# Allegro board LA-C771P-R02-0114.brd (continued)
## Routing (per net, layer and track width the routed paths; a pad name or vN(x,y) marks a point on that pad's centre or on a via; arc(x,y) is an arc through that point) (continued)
GNDA: length 136.1
  TOP w0.102: v3(31.78,19.95) 31.78,20.47 v2(31.88,20.56) ; v2(14.32,12.93) 13.96,13.29 RA24.2 ; v3(28.48,15.12) v2(28.48,14.45)
  TOP w0.203: UA1.25 22.57,21.1 22.48,21.01 22.23,21.01 v3(21.97,21.27)
  TOP w0.254: v3(17.91,17.63) 18.19,17.36 RA14.1 ; UA1.38 28.65,22.68 v3(28.73,22.59)
  TOP w0.381: 22.31,19.06 v3(22.31,18.98) ; 22.31,19.06 22.68,19.43 22.68,19.53 CA20.2 ; 22.31,19.06 22.26,19.01 21.65,19.01 CA16.1 ; RA22.1 v3(27.19,15.12) ; v3(31.4,20.96) 31.33,20.96 30.46,21.83 CA9.2 ; v3(28.48,15.12) RA23.1
  TOP w0.457: v3(15.42,25.03) 15.65,25.26 RA21.2
  TOP w0.508: RA28.2 31.96,19.77 v3(31.78,19.95) ; CA8.2 17.13,19.28 CA7.2 v3(17.1,20.02) ; v3(12.41,13.29) 12.41,13.29 RA24.2 ; RA26.2 v3(30.01,15.76) ; CA11.2 13.14,14.46 CA14.2 12.27,14.44 v3(12.27,14.44)
  IN1 w1.016: 17.48,26.86 18.27,27.64 18.27,32.5 22.41,36.64 22.41,50.28 27.26,55.13 27.26,73.67 26.14,74.79 ; 26.5,78.39 27.41,78.39 29.55,76.26 29.55,54.18 24.7,49.33 24.7,35.7 20.56,31.56 20.56,26.17 v3(20.43,26.04) 19.82,25.43 19.82,23.68 19.64,23.51 19.64,21.93 20.3,21.27 v3(21.97,21.27)
  BOTTOM w0.381: v3(15.27,19.57) 15.53,19.82 CA17.2 15.53,20.18 14.64,20.18 CA19.2
  vias: v3(0.52,21.83) v3(0.49,13.95) v3(1.73,19.39) v3(1.73,16.32) v3(4.05,19.14) v3(4.61,22.39) v3(5.67,20.51) v3(6.79,22.31) v3(7.4,19.24) v3(9.53,16.16) v3(17.1,20.84) v3(25.23,75.14) v3(25.26,74.46) v3(25.38,78.83) v3(25.36,78.16)
VCC_3.3V: length 2.9
  BOTTOM w0.102: v2(50.45,47.84) 50.31,47.98 48.57,47.98 PC320.1
VDD_DDR: length 1.5
  BOTTOM w0.102: 155.58,27.82 156.04,27.36 v2(156.88,27.36)
VIN: length 334.3
  TOP w0.102: v2(44.29,58.18) 44.29,58.17 43.72,58.75 v3(43.72,59.37) v2(43.72,60.14) ; v3(202.92,76.53) 202.33,76.53 201.95,76.15 v2(201.95,76.15)
  IN1 w0.508: v3(43.72,59.37) 43.07,60.02 43.07,66.27 44.7,67.9 44.7,74.27 36.69,82.28 36.69,85.15 43.21,91.68 v3(43.21,94.48)
  IN2 w0.508: v3(43.72,59.37) 43.47,59.12 43.47,55.9 35.33,47.76 34.83,47.26 34.83,35.29 42.58,27.54 43.82,27.54 57.6,13.76 61.08,13.76 63.08,11.76 69.98,11.76 70.38,12.15 77.54,12.15 79.42,14.03 86.03,14.03 86.52,13.53 90.15,13.53 91.3,12.38 103.65,12.38 105.36,14.09 125.31,14.09 129.69,9.71 164.47,9.71 179.5,24.74 179.5,28.76 183.11,32.38 183.11,42.02 185.25,44.15 185.25,57.63 178.23,64.66 178.23,64.69 178.06,64.86 178.06,81.61 180.91,84.46 199.63,84.46 202.52,81.57 202.52,76.92 v3(202.92,76.53)
  BOTTOM w0.508: v3(202.92,76.53) PR215.1 202.23,77.62 PD1.3
+CARD_3V3: length 3.6
  TOP w0.102: v2(47.7,20.71) 47.7,20.71 v3(46.21,20.71) ; v2(45.55,20.04) 45.55,20.05 v3(46.21,20.71) ; v3(46.21,20.71) 46.21,21.86 v2(46.2,21.87)
+CARD_3V3_R: length 0.8
  TOP w0.254: UR1.10 v3(44.53,13.23)
  vias: v2(51.19,21.5)
+CHGRTC: length 4.6
  TOP w0.102: v3(145.33,18.2) v2(145.33,18.79)
  BOTTOM w0.508: v3(145.33,18.2) 145.95,18.2 146.6,17.55 PD100.2 147.88,17.92 PR115.1
+CHGRTC_R: length 11
  TOP w0.102: v3(151.68,16.52) 151.68,17.12 v2(151.68,17.12)
  BOTTOM w0.508: JRTC1.1 158.82,16.52 v3(151.68,16.52) PR116.2
+DDR_A_VREF_CA: length 4.8
  TOP w0.254: v3(107.13,40.13) 107.13,39.68 106.84,39.39 CD3.1 106.84,38.13 RD3.2 RD4.2
  BOTTOM w0.356: JDIMM1.126 107.03,40.05 107.12,40.14 107.12,40.13 v3(107.13,40.13)
+DDR_A_VREF_DQ: length 9
  TOP w0.508: v3(67.47,43.82) 68.11,43.82 68.5,44.22 68.5,45.73 68.22,46.01 RD2.2 68.22,46.33 CD1.1 68.24,47.23 RD1.2
  BOTTOM w0.356: v3(67.47,43.82) 67.16,43.82 66.58,44.4 66.58,45.25 67.13,45.8 JDIMM1.1
+DDR_SOC_VREF: length 14.2
  IN1 w0.254: v3(110.6,68.76) 110.64,68.76 114.55,64.86 117.08,64.86 117.71,64.22 v3(117.71,63.89)
  BOTTOM w0.254: UC4.AF44 110.25,69.12 v3(110.6,68.76)
  BOTTOM w0.508: v3(117.71,63.89) 117.33,63.51 116.75,63.51 116.11,62.87 CC1.1 116.12,62.39 RC7.2 RC6.2
+EC_VCCA: length 40.7
  TOP w0.203: 66.33,10.29 66.53,10.49 UB1.67
  TOP w0.508: v3(67.77,15.88) 67.77,15.5 66.78,14.51 66.3,14.51 64.62,12.83 64.62,12.27 63.53,11.18 62.31,11.18 v2(60.49,9.36) 60.08,8.95 v3(60.08,8.46) ; v3(81.67,18.6) 82.02,18.95 PR110.1 ; v3(65.23,7.93) 65.23,7.52 L3.2 66.26,7.63 CB1.1 66.25,8.27 CB2.1 65.95,9.45 65.95,9.91 66.33,10.29
  IN1 w0.508: v3(60.08,8.46) 60.61,7.93 v3(65.23,7.93)
  BOTTOM w0.508: v3(67.77,15.88) 69.76,17.87 71.58,17.87 72.88,16.57 79.64,16.57 v3(81.67,18.6)
+HDMI_5V_OUT: length 6
  BOTTOM w0.102: v2(14.39,96.25) 14.38,96.25 14.38,95.41 ; v2(16.15,96.16) 15.12,96.16 14.73,95.77 14.73,95.5 ; v2(16.81,94.46) 15.3,94.46
  BOTTOM w0.254: RPY1.2 17.55,90.19 v3(17.33,90.41) 17.05,90.13 RPY1.1
  vias: v3(12.86,94.5) v3(13.16,95.03) v3(13.37,94.12) v3(13.55,90.64) v3(13.6,90.03)
+INVPWR_B+:
  vias: v2(75.05,98.21) v3(66.81,98.76) v3(67.4,98.76) v3(72.25,100.75) v3(73.85,100.82) v3(73.82,100.19)
+IOVDD_CODEC: length 1
  TOP w0.254: UA1.9 23.77,28.53 v3(23.81,28.56)
+LAN_VDD: length 5.5
  TOP w0.508: CL5.1 35.57,66.24 v3(35.07,65.74)
  BOTTOM w0.203: v3(35.07,65.74) 35.07,66.71 UL1.30 ; CL6.1 39.82,67.67 39.73,67.67 39.17,68.23 38.54,68.23 38.46,68.15 UL1.22 ; UL1.3 32.77,68.15 v3(32.7,68.08)
  vias: v2(33.41,66.58) v3(32.75,69.63) v3(32.8,70.21) v3(38.36,66.4) v3(38.7,65.92) v3(38.95,66.46)
+LCDVDD: length 9.8
  TOP w0.127: v2(68.96,85.01) 69.87,85.01 71.46,86.6 ; v2(67.13,85.19) 67.36,85.42 69.73,85.42 71.18,86.86 71.31,86.86 ; v2(70.77,85.21) 71.97,86.41 UX1.1
  vias: v3(63.07,98.76) v3(63.65,98.76) v3(64.24,98.76) v3(64.83,98.78) v3(68.38,91.27) v3(68.41,90.69) v3(69.02,91.27) v3(69.02,90.69) v3(69.63,90.66)
+LINE1-VREFO-L: length 6.9
  TOP w0.203: UA1.31 24.97,20.38 25.48,19.87 v2(25.48,19.59) 25.48,19.37 26.07,18.79 RA25.1 25.56,18.17 25.56,17.38 26.51,16.43 v3(26.55,16.43)
  BOTTOM w0.203: v3(26.55,16.43) 26.25,16.73 RA29.1
+LINE1-VREFO-R: length 1.6
  TOP w0.203: UA1.30 24.57,19.97 RA27.2
+MIC2-VREFO: length 12.4
  TOP w0.203: v3(24.11,20.63) 24.11,20.64 24.16,20.64 24.16,20.69 24.17,20.7 UA1.29
  TOP w0.508: v3(17.81,24.77) RA7.1 RA6.1
  IN2 w0.508: v3(24.11,20.63) 24.11,21.14 23.86,21.4 22.82,21.4 21.6,22.61 21.6,24.7 20.96,25.33 18.37,25.33 v3(17.81,24.77)
+RTCVCC: length 262.4
  TOP w0.508: CC23.1 93.88,92.84 v3(94.01,92.72) 94.01,90.29 93.07,89.34 93.07,88.37 v3(92.98,88.28) 89.87,88.28 89.16,88.99 v3(89.16,89.72) ; v3(118.22,17.99) 118.22,7.63 v2(116.31,5.72) 115.27,4.68 102.52,4.68 101.4,3.56 97.84,3.56 95.42,5.98 v3(93.84,5.98)
  IN1 w0.508: v3(89.16,89.72) 89.16,88.34 88.5,87.68 87.05,87.68 83.6,84.23 81.47,84.23 80.86,83.62 74.42,83.62 73.43,82.62 70.87,82.62 68.23,79.98 67.2,79.98 62.27,75.05 61.43,75.05 61.42,75.04 61.33,75.04 58.37,72.07 56.34,72.07 55.62,72.8 v3(55.62,73.44) ; v3(43.8,73.08) 43.8,68.13 42.22,66.56 42.22,53.02 35.14,45.93 35.14,33.22 37.19,31.17 37.19,27.85 39.94,25.1 39.94,13.07 41.89,11.12 43.03,11.12 44.61,9.53 53.02,9.53 55.46,7.1 65.51,7.1 66.04,7.63 72.53,7.63 73.24,8.34 81.16,8.34 82.23,9.41 82.23,10.24 82.58,10.6 83.09,10.6 83.89,9.8 88.59,9.8 92.41,5.98 v3(93.84,5.98)
  IN2 w0.508: v3(118.22,17.99) 127.64,17.99 v3(129.88,15.76)
  BOTTOM w0.254: UC4.P22 104.7,80.13 v3(104.7,80.37)
  BOTTOM w0.508: RC47.1 92.88,87.65 RC49.1 92.88,88.18 v3(92.98,88.28) ; v3(129.88,15.76) 130.47,15.17 144.19,15.17 PD100.1 ; v3(55.62,73.44) 55.62,73.44 53.75,73.44 52.71,72.4 44.48,72.4 v3(43.8,73.08)
+SOC_VCC: length 1
  BOTTOM w0.508: PC768.2 127.57,69.76 v3(127.06,69.25)
  vias: v2(141.08,73.72) v3(104.8,77.5) v3(105.72,76.31) v3(105.77,77.07) v3(106.49,77.06) v3(106.5,76.29) v3(107.32,76.31) v3(108.09,77.84) v3(108.06,77.1) v3(108.08,76.31) v3(108.85,77.83) v3(108.88,76.31) v3(109.66,77.78) v3(109.66,77.07) v3(110.42,77.78) v3(110.44,77.07) v3(110.44,76.31) v3(118.74,76.42) v3(119.44,76.43) v3(120.19,72.59) v3(122.1,71.71) v3(123.78,68.67) v3(123.76,67.75) v3(135.03,72.72) v3(135.67,72.72) v3(136.56,72.72) v3(137.52,72.66) v3(138.18,72.66) v3(139.1,72.65) v3(139.81,72.64) v3(142.8,73.97) v3(142.83,73.28) v3(143.06,71.28) v3(143.06,70.62) v3(143.08,69.65) v3(143.08,68.99) v3(143.49,73.33) v3(143.59,73.97) v3(144.15,73.33) v3(144.23,68.43) v3(144.25,73.97) v3(144.25,69.17) v3(144.81,73.33) v3(144.94,74) v3(144.94,68.43) v3(144.96,69.17) v3(145.5,73.31) v3(145.6,74) v3(145.65,69.17) v3(145.62,68.43) v3(146.34,69.14) v3(146.31,68.41)
+SOC_VNN: length 2.4
  TOP w0.508: v3(122.92,81.08) 122.92,81.46 122.61,81.77 121.16,81.77 RC71.1
  vias: v2(140.98,77.91) v3(108.85,80.1) v3(108.88,79.34) v3(109.66,79.37) v3(110.45,79.35) v3(110.45,78.59) v3(111.22,79.35) v3(111.97,80.1) v3(112.01,79.35) v3(112.78,80.12) v3(112.77,79.35) v3(112.77,77.82) v3(112.79,77) v3(112.79,76.26) v3(112.78,75.56) v3(129.98,81.82) v3(129.98,81.03) v3(129.98,80.1) v3(129.95,79.33) v3(134.93,79.13) v3(134.97,77.67) v3(135.62,79.1) v3(135.61,77.67) v3(136.74,79.13) v3(136.69,77.73) v3(137.35,77.76) v3(137.4,79.13) v3(138.08,79.14) v3(138.07,77.76) v3(138.74,79.14) v3(138.73,77.78) v3(140.11,80.78) v3(140.3,80.07) v3(140.84,80.81) v3(140.96,80.07) v3(141.6,80.78) v3(141.62,80.07) v3(142,79.34) v3(142.31,80.04) v3(142.43,80.77) v3(142.65,79.32) v3(142.97,80.04) v3(143.12,80.77) v3(143.49,79.39) v3(143.63,80.04) v3(143.8,80.78) v3(144.15,79.37) v3(144.29,80.1)
+USB3_VCCA: length 3.8
  TOP w0.102: v2(22.68,33.63) 22.68,35.38 22.78,35.48
  BOTTOM w0.381: DS2.5 v3(20.42,44.7)
  BOTTOM w0.508: DS3.5 v3(17.46,35.37)
  vias: v2(22.12,35.26) v2(23.71,36) v3(19.34,39.2) v3(19.34,38.44) v3(20.05,39.18) v3(19.97,38.49) v3(20.68,39.2) v3(20.68,38.52)
+USB_SB:
  vias: v2(184.67,51.57) v3(186.24,53.86) v3(186.24,53.09) v3(186.24,52.33) v3(186.24,51.57) v3(186.24,50.68) v3(197.14,54.82) v3(198.03,54.82) v3(199.04,54.85) v3(200.13,54.82) v3(201.1,54.8)
ACDRV: length 322.4
  IN1 w0.508: v3(38.62,82.23) 38.62,81.25 45.33,74.53 45.33,67.63 43.88,66.18 43.88,60.22 44.38,59.72 44.38,59.04 v3(44.28,58.94)
  IN2 w0.508: v3(200.24,74.58) 200.49,74.58 201.13,75.22 203.36,75.22 203.92,75.78 203.92,77.66 203.51,78.06 203.51,81.8 199.91,85.4 180.95,85.4 177.43,81.87 177.43,64.59 177.59,64.43 177.59,64.39 184.61,57.37 184.61,44.42 182.48,42.28 182.48,32.66 178.86,29.05 178.86,25 164.21,10.35 129.95,10.35 125.57,14.73 105.1,14.73 103.38,13.01 91.57,13.01 90.41,14.17 86.78,14.17 86.29,14.66 79.15,14.66 77.27,12.79 70.11,12.79 69.72,12.39 63.35,12.39 61.34,14.39 57.86,14.39 44.06,28.2 42.82,28.2 35.59,35.43 35.59,47.13 44.28,55.82 v3(44.28,58.94)
  BOTTOM w0.203: PU1.4 200.38,74.23 200.24,74.37 v3(200.24,74.58)
  BOTTOM w0.508: v3(38.62,82.23) 38.92,82.23 39.53,82.84 PR209.2
ACN: length 359.9
  IN2 w0.254: v3(198.28,77.16) 198.28,77.46 199.42,78.6 200.11,78.6 200.57,79.05 200.57,80.17 198.61,82.13 188.91,82.13 186.67,79.89 183.95,79.89 181.39,77.33 181.39,67.09 184.61,63.86 197.9,63.86 198.48,63.29 202.46,63.29 204.83,60.92 204.83,31.03 179.94,6.13 128,6.13 123.85,10.28 108.96,10.28 108.46,10.78 91.59,10.78 89.73,12.65 86.15,12.65 85.66,13.14 79.82,13.14 77.94,11.26 70.75,11.26 70.35,10.87 62.42,10.87 60.56,12.73 57.1,12.73 43.66,26.17 42.52,26.17 33.81,34.88 33.81,50.41 37.3,53.89 38.78,53.89 41.66,56.78 41.66,59.98 46.66,64.98 48.34,64.98 48.75,65.39 48.75,68.31 49,68.56 49,74.58 v3(49.36,74.94)
  BOTTOM w0.203: PC210.1 198.8,73.78 199.18,73.41 PU1.1
  BOTTOM w0.254: v3(49.36,74.94) 49.18,74.76 45.58,74.76 44.87,75.46 40.78,75.46 39.2,77.05 v2(39.2,77.58) 39.2,79.1 39.28,79.18 39.28,81.01 39.71,81.44 41.87,81.44 42.07,81.24 PR202.3 ; PC210.1 198.84,74.41 PC208.2 198.45,75.64 198.45,75.67 PC209.1 198.28,76.48 v3(198.28,77.16)
ACP: length 360.9
  IN2 w0.254: v3(198.98,77.17) 198.98,77.62 199.58,78.22 200.27,78.22 200.95,78.9 200.95,80.33 198.77,82.51 188.75,82.51 186.51,80.27 183.8,80.27 181.01,77.48 181.01,66.93 184.46,63.48 197.75,63.48 198.32,62.91 202.3,62.91 204.45,60.76 204.45,31.18 179.78,6.51 128.16,6.51 124,10.66 109.11,10.66 108.62,11.16 91.75,11.16 89.89,13.03 86.31,13.03 85.81,13.52 79.66,13.52 77.78,11.64 70.59,11.64 70.19,11.25 62.58,11.25 60.71,13.12 57.26,13.12 43.82,26.55 42.68,26.55 34.19,35.04 34.19,50.25 37.46,53.51 38.94,53.51 42.04,56.62 42.04,59.83 46.82,64.6 48.5,64.6 49.13,65.23 49.13,68.15 49.39,68.41 49.39,74.08 v3(49.79,74.48)
  BOTTOM w0.203: PC208.1 199.36,74.86 199.36,73.73 199.58,73.52 PU1.2
  BOTTOM w0.254: PR202.2 42.07,82.03 41.87,81.82 39.55,81.82 38.82,81.09 v2(38.82,79.46) 38.82,77.85 38.74,77.77 38.74,77.39 38.82,77.31 38.82,76.89 40.62,75.08 44.71,75.08 45.42,74.38 49.69,74.38 v3(49.79,74.48) ; v3(198.98,77.17) PC207.2 199.38,75.94 199.38,75.63 PC208.1
ADP_I: length 222.9
  TOP w0.203: v3(63.33,9.56) 63.89,10.12 64.87,10.12 65.73,10.98 UB1.65
  TOP w0.254: PR112.2 88.73,14 92.74,9.99 93.99,9.99 v3(94.65,9.33) ; v3(201.9,73.86) 201.9,73.48 201.58,73.16
  IN2 w0.254: v3(63.33,9.56) 64.22,10.45 70.62,10.45 71.05,10.88 78.1,10.88 79.98,12.76 85.5,12.76 85.99,12.26 89.57,12.26 91.49,10.35 93.63,10.35 v3(94.65,9.33) 95.71,10.4 108.3,10.4 108.8,9.9 123.69,9.9 127.95,5.63 179.98,5.63 207.2,32.85 207.2,40.56 205.85,41.91 205.85,64.12 204.25,65.72 204.25,72.98 203.28,73.95 201.99,73.95 v3(201.9,73.86)
  BOTTOM w0.203: PU1.7 201.58,73.41 201.9,73.73 v3(201.9,73.86)
APDIN: length 4.6
  TOP w0.102: v3(39.3,100.94) 39.28,100.94 38.96,101.25 37.09,101.25 v2(37.03,101.19) ; v3(39.3,100.94) 40.08,100.94 v2(40.18,101.04) ; v3(39.3,100.94) 38.49,100.12 v2(38.43,100.12)
APDIN1:
  vias: v2(49.08,97.95)
B+:
  vias: v2(176.68,75.47) v2(181.25,78.24) v2(181.73,73.39) v3(46.12,52.94) v3(46.76,52.94) v3(47.39,52.94) v3(48.03,52.91) v3(49.31,75.8) v3(49.82,76.21) v3(50.25,76.69) v3(50.4,75.88) v3(50.71,77.17) v3(50.83,76.36) v3(56.42,53.17) v3(56.93,50.86) v3(57.09,48.14) v3(57.18,53.15) v3(57.18,52.46) v3(57.31,48.78) v3(57.56,50.43) v3(57.75,52.74) v3(57.82,49.79) v3(57.76,48.33) v3(58.2,52.21) v3(137.45,28.41) v3(137.37,27.69) v3(137.4,27.06) v3(138.13,28.41) v3(138.16,29.12) v3(138.16,27.75) v3(138.21,27.01) v3(138.8,28.46) v3(138.8,27.78) v3(138.87,29.8) v3(138.89,29.09) v3(175.93,47.9) v3(175.93,43.43) v3(175.95,47.14) v3(175.95,46.38) v3(175.95,45.41) v3(175.95,44.34) v3(175.95,42.46) v3(176.69,47.97) v3(176.72,46.48) v3(176.69,45.43) v3(176.72,44.39) v3(176.67,43.45) v3(176.72,42.52) v3(176.77,47.16)
BA+: length 19.1
  TOP w0.102: v2(194.45,76.27) 194.39,76.34 v3(192.63,76.34)
  IN2 w0.508: v3(187.49,77.42) 190.53,80.46 198.8,80.46 v3(199.73,79.54)
  BOTTOM w0.508: PC201.2 v3(187.49,77.42) ; PD1.2 201.61,79.54 v3(199.73,79.54)
  vias: v3(191.93,76.34) v3(191.93,75.64) v3(191.93,74.94) v3(191.93,74.24) v3(192.63,75.64) v3(192.63,74.94) v3(192.63,74.24)
BATDRV: length 30.7
  TOP w0.254: v3(201.77,67.45) 203.06,67.45 204.81,69.19 204.81,72.43 204.26,72.98 v2(204.26,76.82) 204.26,79.44 203.04,80.65 192.07,80.65 PR212.2
  BOTTOM w0.203: PU1.18 200.38,68.33 201.26,67.45 v3(201.77,67.45)
BATSRC: length 28.4
  TOP w0.254: v3(202.22,67.95) 203.03,67.95 204.38,69.3 204.38,72.32 203.78,72.92 v2(203.78,78.57) 203.78,79.22 202.73,80.27 192.68,80.27 v3(192.04,79.64)
  BOTTOM w0.203: v3(202.22,67.95) 201.26,67.95 200.78,68.44 PU1.17
  BOTTOM w0.254: v3(192.04,79.64) PR213.2
BATT+:
  vias: v2(200.21,83.98) v3(195.3,79.4) v3(195.27,78.74) v3(195.27,78.08) v3(195.27,77.42) v3(196.02,79.4) v3(195.99,78.74) v3(195.99,78.08) v3(195.99,77.42)
BATT_CHG_LED#: length 63.2
  TOP w0.102: UB1.90 75.73,10.69 76.59,9.83 76.59,7.37 76.37,7.15 76.37,5.38 75.01,4.02 v3(75.01,3.89) ; R15.1 25.08,6.89 v3(25.69,6.89)
  IN2 w0.127: v3(25.69,6.89) 28.48,6.89 29.27,6.1 31.77,6.1 35.78,2.1 74.09,2.1 75.01,3.02 v3(75.01,3.89)
BATT_LOW_LED#: length 71.3
  TOP w0.102: 77.28,10.52 76.93,10.87 UB1.93 ; 77.28,10.52 77.28,10.52 77.27,10.52 77.27,7.09 77.05,6.87 77.05,4.21 v3(76.82,3.97) ; 77.28,10.52 v2(77.28,10.33) ; LED2.1 v3(20.75,1.6)
  IN2 w0.127: v3(76.82,3.97) 76.82,3.75 74.4,1.33 31.8,1.33 29.09,4.05 29.09,5.11 28.17,6.03 25.38,6.03 20.95,1.6 v3(20.75,1.6)
BEEP#: length 55.7
  TOP w0.102: UB1.23 69.33,26.34 69.68,25.99 v3(69.68,21.42)
  BOTTOM w0.102: CA30.1 25.31,29.5 25.92,30.11 29.32,30.11 v2(29.47,30.26) 34.27,30.26 37.05,27.49 55.84,27.49 57.3,26.03 61.02,26.03 61.41,25.64 61.41,25.26 62.4,24.26 65.31,24.26 68.16,21.42 v3(69.68,21.42)
BKOFF#: length 56.8
  TOP w0.102: RPC1.5 79.56,75.09 79.43,74.96 79.43,74.58 78.53,73.67 78.53,73.26 73.84,68.57 67.79,68.57 67.65,68.72 65.61,68.72 64.89,69.44 63.64,69.44 61.87,71.21 61.87,76.64 59.66,78.85 57.16,78.85 55.91,77.61 54.13,77.61 v3(53.86,77.88)
  IN1 w0.127: v3(53.86,77.88) 53.5,78.24 53.5,85.05 50.33,88.22 50.33,91.14 v3(51.37,92.18)
  BOTTOM w0.102: v3(53.86,77.88) 53.58,77.61 53.29,77.32 v2(53.02,77.32) 52.79,77.55 RC8.2 ; RX6.1 51.37,92.79 v3(51.37,92.18)
BOOT1: length 1.4
  BOTTOM w0.102: PR730.2 150.38,64.41 150.31,64.47 v2(149.84,64.47)
BOOTG:
  vias: v2(159.01,63.25)
BQ24780VDD: length 3.9
  TOP w0.381: PC213.1 v2(198.41,71.84) 198.41,71.89 198.78,72.26 PR228.1
  TOP w0.508: PC213.1 197.31,70.39 v3(197.29,70.37)
BST_3V: length 0.8
  TOP w0.102: v2(188.65,40.85) v3(189.19,40.32)
BST_5V: length 0.7
  TOP w0.102: v3(47.2,48.42) v2(47.2,49.11)
BST_CHG:
  vias: v2(197.21,70.93)
BST_DDR:
  vias: v1(150.99,31.41)
BST_DDR_R:
  vias: v2(149.51,26.91)
BT_OFF#: length 87.5
  IN1 w0.127: v3(100.43,96.54) 100.43,96.94 103.22,99.72 120.16,99.72 120.68,99.2 125.17,99.2 126.4,100.44 139.06,100.44 143.35,96.15 143.35,95.56 149.79,89.12 153.98,89.12 154.5,89.65 154.86,89.65 155.7,88.81 156.14,88.81 156.48,89.15 161.67,89.15 161.96,89.44 165.84,89.44 167.83,87.45 168.83,87.45 169.53,88.15 170.05,88.15 170.58,87.61 v3(170.58,87.02)
  BOTTOM w0.102: RC80.1 101.58,95.08 v2(101.3,95.08) 100.43,95.95 v3(100.43,96.54) ; v3(170.58,87.02) 170.21,86.65 RM19.1 170.73,86.11 170.89,86.27 170.89,86.74 171.28,87.13 171.61,87.13 171.73,87.25 QM1.2
BT_OFF#_R: length 3.4
  BOTTOM w0.102: UC4.K2 102.36,90.69 102.57,90.9 v2(102.57,92.26) RC80.2
CAPS_LED#: length 56.6
  TOP w0.102: v3(75.6,3.97) 75.6,4.28 76.6,5.28 76.6,7.06 76.82,7.28 76.82,9.92 76.13,10.61 UB1.91 ; LED4.1 31.8,1.6 v2(32.42,2.22) v3(33.31,3.11)
  IN2 w0.127: v3(75.6,3.97) 75.6,3.24 74.19,1.84 34.57,1.84 v3(33.31,3.11)
CARD_CLKREQ#: length 271.1
  TOP w0.102: UR1.24 50.57,14.73 53.68,17.84 v3(53.68,21.04) ; v3(119.39,87.53) 119.87,88.02 120.58,88.02 121.86,89.3 122.52,89.3 122.74,89.51 122.74,90.89 124.85,93 RPC3.4
  IN2 w0.102: v3(119.39,87.53) 119.48,87.44 122.41,87.44 122.71,87.13
  IN2 w0.127: 122.71,87.13 122.84,87 131.11,87 131.73,86.38 140.16,86.38 142.25,88.46 149.52,88.46 149.76,88.7 153.74,88.7 154.4,88.03 164.22,88.03 167.27,84.98 168.12,84.98 172.5,80.6 172.5,63.49 179.1,56.89 179.1,55.13 181.5,52.73 181.5,45.71 179.33,43.53 179.33,33.97 160.59,15.22 132.53,15.22 129.07,18.69 109.52,18.69 109.15,18.32 102.16,18.32 101.68,17.85 99.59,17.85 98.99,18.45 92.92,18.45 92.6,18.76 87.66,18.76 87.15,18.25 84.96,18.25 84.03,19.17 78.84,19.17 77.38,17.71 75.57,17.71 73.95,16.09 73.95,15.6 73.64,15.3 71.23,15.3 70.66,15.86 68.66,15.86 67.16,14.36 64.33,14.36 57.87,20.82 53.9,20.82 v3(53.68,21.04)
  BOTTOM w0.102: UC4.BD7 119.01,87.16 v3(119.39,87.53)
CLK_PCIE_CARD: length 170.6
  TOP w0.102: UR1.3 47.68,15.81 47.48,16.01 47.48,16.34 47.58,16.44 v3(47.81,16.44)
  IN2 w0.127: v3(110.65,87.72) 110.52,87.58 110.35,87.58 106.82,91.12 104.86,91.12 101.34,94.63 100.07,94.63 97.86,96.84 87.09,96.84 85.16,94.92 79.58,94.92 76.33,91.67 71.25,91.67 70.86,92.07 66.16,92.07 65.84,92.38 56.09,92.38 54.91,91.21 49.43,91.21 40.02,81.8 40.02,71.44 37.8,69.22 37.8,67.4 37.42,67.01 34.6,67.01 33.69,66.1 33.69,65.36 31.46,63.14 31.46,58.53 25.86,52.93 25.86,34.99 28.95,31.9 31.42,31.9 34.34,28.98 34.34,27.86 40.61,21.59 40.61,18.24 43.09,15.75 47.35,15.75 47.64,16.05 47.64,16.27 v3(47.81,16.44)
  BOTTOM w0.102: v3(110.65,87.72) 110.14,87.2 UC4.AF7
CLK_PCIE_CARD#: length 170.6
  TOP w0.102: UR1.4 47.18,15.91 47.26,15.99 47.26,16.36 v3(47,16.61)
  IN2 w0.127: v3(47,16.61) 47.31,16.61 47.38,16.55 47.38,16.16 47.24,16.02 43.2,16.02 40.88,18.35 40.88,21.7 34.6,27.97 34.6,29.09 31.53,32.17 29.07,32.17 26.13,35.1 26.13,52.82 31.73,58.42 31.73,63.03 33.95,65.25 33.95,65.99 34.71,66.75 37.53,66.75 38.07,67.28 38.07,69.11 40.29,71.33 40.29,81.69 49.54,90.94 55.02,90.94 56.2,92.12 65.73,92.12 66.05,91.8 70.75,91.8 71.14,91.41 76.45,91.41 79.69,94.65 85.27,94.65 87.2,96.58 97.75,96.58 99.96,94.36 101.23,94.36 104.75,90.85 106.7,90.85 110.24,87.32 110.63,87.32 110.8,87.14 110.8,86.8 v3(110.6,86.6)
  BOTTOM w0.102: UC4.AF9 110.13,86.74 110.22,86.84 110.36,86.84 v3(110.6,86.6)
CLK_PCIE_LAN: length 104.7
  IN2 w0.127: v3(110.65,88.32) 109.86,89.11 109.86,90.58 108.75,91.69 107.28,91.69 106.51,92.45 104.51,92.45 101.5,95.47 100.5,95.47 98.49,97.48 86.79,97.48 84.86,95.55 79.16,95.55 77.85,94.24 71.68,94.24 71.41,93.97 48.29,93.97 37.38,83.07 37.38,80.76 37.61,80.54 38.13,80.54 38.51,80.16 38.51,79.62 38.13,79.24 37.61,79.24 37.38,79.02 37.38,78.71 37.61,78.48 38.13,78.48 38.51,78.1 38.51,77.57 38.13,77.19 37.61,77.19 37.38,76.96 37.38,76.65 37.61,76.43 38.13,76.43 38.51,76.05 38.51,75.51 38.13,75.13 37.61,75.13 37.38,74.91 37.38,72.57 37.73,72.22 37.98,72.22 38.09,72.33 v3(38.09,72.79)
  BOTTOM w0.089: UC4.AK6 111.54,87.91 111.23,88.22 110.75,88.22 v3(110.65,88.32)
  BOTTOM w0.102: UL1.15 36.67,71.17 36.78,71.28 36.78,71.73 37.46,72.41 37.71,72.41 v3(38.09,72.79)
CLK_PCIE_LAN#: length 104.7
  IN2 w0.127: v3(110.68,88.98) 110.37,88.98 110.13,89.22 110.13,90.69 108.86,91.96 107.39,91.96 106.62,92.72 104.62,92.72 101.61,95.74 100.61,95.74 98.6,97.74 86.68,97.74 84.75,95.82 79.05,95.82 77.74,94.51 71.57,94.51 71.3,94.24 48.18,94.24 37.12,83.18 37.12,80.65 37.49,80.27 38.02,80.27 38.24,80.05 38.24,79.73 38.02,79.51 37.49,79.51 37.12,79.13 37.12,78.6 37.49,78.22 38.02,78.22 38.24,77.99 38.24,77.68 38.02,77.45 37.49,77.45 37.12,77.07 37.12,76.54 37.49,76.16 38.02,76.16 38.24,75.94 38.24,75.62 38.02,75.4 37.49,75.4 37.12,75.02 37.12,72.46 37.62,71.95 37.95,71.95 v3(38.09,71.81)
  BOTTOM w0.089: v3(110.68,88.98) 110.77,88.88 110.97,88.88 110.97,88.89 111.22,88.89 111.22,88.88 111.79,88.88 UC4.AK4
  BOTTOM w0.102: v3(38.09,71.81) 38.09,71.93 37.83,72.2 37.55,72.2 37,71.64 37,71.26 37.07,71.19 UL1.16
CLK_PCIE_WLAN: length 105.3
  IN2 w0.127: v3(112.68,87.53) 112.68,87.71 112.82,87.85 113.11,87.85 113.37,88.11 113.37,92.74 114.23,93.61 114.23,99.03 113.33,99.93 108.64,99.93 108.44,100.14 108.44,100.52 108.64,100.72 113.84,100.72 114.81,99.75 136.14,99.75 136.55,99.34 136.55,99.02 136.33,98.8 127.85,98.8 127.49,98.44 127.49,97.88 127.85,97.52 141.11,97.52 141.22,97.52 146.38,92.35 146.54,92.19 147.97,92.19 148.74,92.96 162.56,92.96 162.92,92.6 166.06,92.6 166.89,91.78 168.03,91.78 168.47,91.34 168.47,90.65 v3(168.25,90.42)
  BOTTOM w0.102: JWLAN1.13 168.15,90.52 v3(168.25,90.42) ; v3(112.68,87.53) 112.68,87.69 112.91,87.91 UC4.AM6
CLK_PCIE_WLAN#: length 105.4
  IN2 w0.127: v3(112.67,88.22) 112.77,88.12 113,88.12 113.1,88.22 113.1,92.85 113.96,93.72 113.96,98.92 113.22,99.67 108.53,99.67 108.17,100.03 108.17,100.63 108.53,100.99 113.95,100.99 114.92,100.02 136.25,100.02 136.82,99.45 136.82,98.91 136.44,98.53 127.96,98.53 127.76,98.33 127.76,97.99 127.96,97.79 141.11,97.79 141.33,97.79 146.65,92.46 146.65,92.46 147.86,92.46 148.63,93.23 162.67,93.23 163.03,92.87 166.17,92.87 167,92.05 168.14,92.05 168.74,91.45 168.74,90.51 v3(168.83,90.42)
  BOTTOM w0.102: v3(168.83,90.42) 168.95,90.54 JWLAN1.11 ; UC4.AM4 v3(112.67,88.22)
CLR_CMOS#: length 126.5
  TOP w0.102: v3(88.52,89.21) 88.52,88.69 v1(89.48,87.73) v3(90.22,86.99) ; v3(60.95,37.48) 60.94,37.47 57.08,37.47 56.63,37.02 55.84,37.02 51.8,32.97 51.8,32.57 51.8,23.61 54.26,21.14 v3(54.26,14.64)
  BOTTOM w0.102: v3(54.26,14.64) 53.6,13.98 53.6,11.77 58.33,7.04 62.43,7.04 63.72,5.75 67.09,5.75 67.42,6.08 QB1.1 ; v3(88.52,89.21) 88.33,89.02 RC84.2 ; v3(60.95,37.48) 59.98,38.45 59.98,45.01 61.2,46.22 61.2,50.2 69.49,58.48 69.49,69.23 68.43,70.28 68.43,71.49 67.88,72.04 67.88,79.26 70.8,82.18 72.86,82.18 73.52,82.84 85.09,82.84 88.98,86.73 RC83.2 89.96,86.73 v3(90.22,86.99)
CMOS_ON#: length 101.2
  TOP w0.102: UB1.86 74.13,13.29 73.79,13.62 73.79,18.16 v3(73.44,18.52) ; v3(49.56,84.34) 49.03,84.87 46.69,84.87 41.1,79.28 41.1,70.51 41.33,70.28 41.33,58.62 45.36,54.59 49.16,54.59 v3(52.79,50.96)
  IN2 w0.127: v3(52.79,50.96) 52.59,50.76 52.59,49.69 53.56,48.71 53.56,43.09 54.49,42.16 54.49,35.18 55.66,34.01 55.66,33.24 57.33,31.56 57.33,29.52 59.49,27.36 59.49,25.13 62.34,22.28 62.34,21.6 64.4,19.54 65.87,19.54 67.4,18.01 68.71,18.01 69.52,18.83 73.13,18.83 v3(73.44,18.52)
  BOTTOM w0.102: RX11.1 50.32,83.57 v3(49.56,84.34)
CMSRC: length 323.6
  IN1 w0.508: v3(45.02,59.88) 45.02,60.56 44.71,60.87 44.71,66.07 45.97,67.33 45.97,74.8 39.48,81.28 39.48,82.66 38.97,83.17 v3(38.51,83.17)
  IN2 w0.508: v3(45.02,59.88) 45.02,55.65 36.25,46.89 36.25,35.67 43.08,28.83 44.32,28.83 58.13,15.03 61.61,15.03 63.61,13.03 69.46,13.03 70.19,13.76 76.07,13.76 77.42,15.11 78.54,15.11 79.5,16.07 83.45,16.07 84.17,15.35 86.5,15.35 87.05,14.8 90.67,14.8 91.83,13.65 103.12,13.65 104.84,15.36 125.83,15.36 128.9,12.3 165,12.3 178.23,25.53 178.23,29.31 181.84,32.93 181.84,42.55 183.98,44.68 183.98,57.11 176.7,64.38 176.7,82.05 180.69,86.03 200.75,86.03 204.88,81.9 204.88,75.27 204.07,74.46 202.17,74.46 202.15,74.47 201.65,74.47 201.63,74.46 201.61,74.46 200.9,73.75 200.05,73.75 v3(199.87,73.92)
  BOTTOM w0.203: v3(199.87,73.92) 199.98,73.81 PU1.3
  BOTTOM w0.508: PR211.2 v3(38.51,83.17)
CPU_B+:
  vias: v2(159.16,74.08) v3(158.43,73.57) v3(158.43,72.91) v3(159.73,78.83) v3(159.72,78.11) v3(161.5,80.83) v3(161.5,79.97) v3(161.53,78.09) v3(161.5,77.12) v3(161.53,76.11) v3(161.5,75.09)
CPVEE: length 5
  TOP w0.203: UA1.34 26.17,20.79 27.04,19.92 v2(28.02,19.92) 28.51,19.92 29.37,19.06 CA22.2
CS_DDR: length 4.3
  BOTTOM w0.102: PR402.2 152.71,26.64 v2(153.12,26.23)
  BOTTOM w0.203: PU303.13 153.67,28.63 153.16,28.11 153.13,28.11 PR402.2
DBG_UART_RXD: length 1.1
  TOP w0.102: v3(118.6,82.28) 118.73,82.15 T15.1
  BOTTOM w0.102: v3(118.6,82.28) 118.4,82.47 UC4.BC16
DBG_UART_TXD: length 1.2
  TOP w0.102: v3(118.95,84.28) 118.95,84.16 T14.1
  BOTTOM w0.102: v3(118.95,84.28) 119.11,84.12 UC4.BD14
DCHG_I: length 1.3
  TOP w0.102: 202.79,73.16 202.78,73.17 v2(202.78,74.46)
  vias: v3(203.21,72.48)
DDI0_RCOMPN: length 11.6
  TOP w0.254: RC11.1 113.68,94.92 v2(113.68,92.57) 113.68,86.47 112.6,85.38 v3(112.6,84.79)
  BOTTOM w0.254: v3(112.6,84.79) 112.16,84.36 UC4.AK13
DDI0_RCOMPP: length 11.5
  TOP w0.254: v3(111.61,84.88) 111.61,84.92 113.19,86.49 v2(113.19,89.32) 113.19,94.92 RC11.2
  BOTTOM w0.254: v3(111.61,84.88) 111.8,85.07 UC4.AK12
DDI1_ENABLE: length 4.2
  TOP w0.102: v2(104.32,73.88) 103.92,74.29 v3(103.92,74.53) 103.58,74.87 103.15,74.87 102.71,74.44 RC9.1
  BOTTOM w0.102: UC4.P30 104.1,75.64 104.1,74.71 v3(103.92,74.53)
DDI1_ENBKL: length 61.3
  IN2 w0.102: v3(101.66,75.49) 101.66,75.34 101.3,74.99 99.75,74.99 98.02,76.71 95.31,76.71 95.26,76.76 95.15,76.76
  IN2 w0.127: v3(62.22,69.76) 62.26,69.8 70,69.8 76.67,76.46 93.21,76.46 93.51,76.76 95.15,76.76
  BOTTOM w0.102: UC4.J30 101.66,75.95 v3(101.66,75.49) ; 58.96,79.96 v2(58.96,80.96) 58.96,82.08 58.74,82.3 RPC2.8 ; 58.96,79.96 59.14,79.96 59.32,79.78 59.32,78.11 59.19,77.98 59.19,77.32 59.72,76.79 60.03,76.79 60.66,76.16 60.66,71.32 v3(62.22,69.76) ; 58.96,79.96 RC10.1 57.99,79.96 CC2.2 57.64,79.91 57.22,79.5 UC5.2
DDI1_ENVDD: length 63.4
  IN2 w0.102: 95.15,76.51 97.74,76.51 99.46,74.78 102.98,74.78 103.43,75.24 v3(103.43,75.42)
  IN2 w0.127: v3(62.77,69.38) 69.96,69.38 76.79,76.21 93.32,76.21 93.62,76.51 95.15,76.51
  BOTTOM w0.102: v3(62.77,69.38) 62.77,69.84 61.93,70.68 61.93,77.5 62.68,78.25 62.68,78.72 RC13.1 62.99,79.61 UC6.2 61.6,79.61 60.87,80.34 60.87,81.25 60.07,82.05 60.07,82.3 CC3.2 59.45,82.3 58.95,82.8 RPC2.7 ; UC4.N30 103.74,75.9 103.43,75.6 v3(103.43,75.42)
DDI1_PWM: length 66
  TOP w0.102: v3(102.85,75.47) 102.85,75.41 102.5,75.06 102.21,75.06 101.63,74.48 101.63,74.27 100.85,73.49 98.31,73.49 97.63,72.81 87.89,72.81 84.93,75.76 UC7.2 83.23,75.79 81.2,75.79 80.78,75.38 80.78,73.89 74.75,67.85 67.12,67.85 v3(66.94,68.03)
  BOTTOM w0.102: v3(66.94,68.03) 66.77,68.03 62.75,72.06 62.75,76.44 63.82,77.51 63.82,82.01 v2(62.83,83.01) 62.13,83.7 60.56,83.7 60.07,83.21 CC4.2 59.58,83.21 59.49,83.3 RPC2.6 ; v3(102.85,75.47) 102.85,75.49 103.03,75.68 UC4.M30
DDR_A_BS0: length 50
  IN2 w0.102: v3(101.97,67.33) 102.27,67.63 102.99,67.63 103.56,67.06 103.99,67.06 104.07,66.98 104.19,66.86 104.19,66.37 104.19,66.37 104.19,65.31 103.93,65.04 103.93,64.23 103.55,63.85 103.55,62.85
  IN2 w0.203: v3(103.23,43.83) 103.11,43.83 102.57,44.36 102.57,48.52 103.45,49.4 103.45,50.17 103.16,50.46 102.02,50.46 101.78,50.7 101.78,51.14 101.99,51.35 103.43,51.35 103.63,51.55 103.63,51.95 103.43,52.16 101.99,52.16 101.78,52.36 101.78,52.77 101.99,52.97 103.43,52.97 103.63,53.17 103.63,53.58 103.43,53.78 101.99,53.78 101.78,53.99 101.78,54.39 101.99,54.6 103.43,54.6 103.63,54.8 103.63,55.21 103.43,55.41 102.23,55.41 101.93,55.71 101.93,61.41 102.16,61.64 102.5,61.64 102.74,61.41 102.74,58.26 102.94,58.06 103.35,58.06 103.55,58.26 103.55,62.85
  BOTTOM w0.102: UC4.K47 v3(101.97,67.33)
  BOTTOM w0.165: v3(103.23,43.83) 102.89,43.83 102.17,44.55 102.17,45.66 101.93,45.9 JDIMM1.109
DDR_A_BS1: length 50.1
  IN2 w0.102: 105.46,62.46 105.46,67.96 105.13,68.29 104.64,68.29 104.5,68.43 104.37,68.56 103.64,68.56 103.42,68.78 103.42,69.16 103.08,69.49 v3(102.76,69.49)
  IN2 w0.203: 105.46,62.46 105.46,62.46 105.46,58.64 108.85,55.26 108.85,52.09 108.59,51.83 107.48,51.83 107.22,51.58 107.22,47.78 105.98,46.54 105.98,44.65 105.7,44.37 105.7,42.65 104.96,41.91 103.83,41.91 102.67,40.76 102.67,39.3 102.87,39.11 106.21,39.11 106.45,38.87 106.45,38.53 106.21,38.29 102,38.29 101.63,38.66 v3(101.63,39.93)
  BOTTOM w0.102: UC4.K44 v3(102.76,69.49)
  BOTTOM w0.165: JDIMM1.108 v3(101.63,39.93)
DDR_A_BS2: length 49.9
  IN2 w0.203: v3(92.41,45.29) 92.41,46.67 91.01,48.06 v3(91.01,48.1)
  BOTTOM w0.102: 95.32,63.34 95.9,63.92 98.13,63.92 98.43,64.22 99.04,64.22 99.25,64.43 99.25,64.98 UC4.D52
  BOTTOM w0.165: v3(91.01,48.1) 91.42,48.51 91.42,54.85 91.23,55.04 90.95,55.04 90.76,54.85 90.76,49.6 90.57,49.4 90.29,49.4 90.1,49.6 90.1,56.44 89.91,56.63 89.63,56.63 89.44,56.44 89.44,52.6 89.25,52.41 88.97,52.41 88.78,52.6 88.78,56.8 95.32,63.34 ; v3(92.41,45.29) 92.93,45.81 JDIMM1.79
DDR_A_CAS#: length 45.6
  IN2 w0.102: v3(102.78,68.83) 102.46,68.51 102.46,68.08 102.7,67.83 103.08,67.83 103.65,67.26 104.15,67.26 104.4,67.01 104.4,63.81 104.24,63.65 104.24,63.11
  IN2 w0.203: v3(104.43,44.68) 104.43,44.82 104.76,45.15 104.76,45.86 104.46,46.16 104.46,46.75 105.87,48.16 105.87,54.71 106.08,54.92 106.65,54.92 106.85,55.12 106.85,55.53 106.65,55.73 106.07,55.73 105.87,55.94 105.87,56.51 105.63,56.75 105.29,56.75 105.06,56.51 105.06,50.31 104.82,50.07 104.48,50.07 104.24,50.31 104.24,63.11
  BOTTOM w0.102: UC4.M44 v3(102.78,68.83)
  BOTTOM w0.165: JDIMM1.115 103.73,44.95 103.99,44.68 v3(104.43,44.68)
DDR_A_CKE0: length 55.2
  IN2 w0.102: v3(99.48,67.84) 98.59,67.84 98.2,67.46 96.87,67.46 96.17,66.75 95.71,66.75
  IN2 w0.203: v3(89.95,45.24) 89.16,45.24 88.91,45.5 88.91,46.24 87.74,47.41 87.74,48.32 87.52,48.54 87.24,48.54 86.45,47.75 86.16,47.75 85.87,48.03 85.87,48.32 86.66,49.11 86.66,49.4 84.29,51.77 82.61,51.77 82.41,51.97 82.41,52.38 82.61,52.58 84,52.58 84.21,52.78 84.21,53.19 84,53.39 82.23,53.39 82.03,53.6 82.03,54 82.23,54.21 84,54.21 84.21,54.41 84.21,54.82 84,55.02 82.62,55.02 82.42,55.22 82.42,55.63 82.62,55.83 84,55.83 84.21,56.03 84.21,58.9 85.02,59.71 85.02,59.99 84.49,60.51 84.49,60.8 84.78,61.09 85.07,61.09 85.59,60.57 85.88,60.57 86.16,60.86 86.16,61.14 85.72,61.59 85.72,62.04 86.41,62.73 86.41,63.61 88.26,65.46 88.88,65.46 89.36,65.95 89.36,66.64 89.84,67.11 92.82,67.11 93.18,66.75 95.71,66.75
  BOTTOM w0.102: UC4.C47 v3(99.48,67.84)
  BOTTOM w0.165: JDIMM1.73 91.13,46.43 v3(89.95,45.24)
DDR_A_CKE2: length 56
  IN2 w0.102: 96.82,68.32 96.95,68.45 97.8,68.45 98.03,68.22 99.99,68.22 v3(100.33,68.56)
  IN2 w0.203: v3(90.66,39.96) 90.66,40.93 89.89,41.7 89.26,41.7 86.8,44.16 86.8,46.18 84.73,48.25 84.73,49.26 83.9,50.09 82.89,50.09 81.41,51.57 81.41,56.39 81.62,56.6 83.38,56.6 83.58,56.8 83.58,57.21 83.38,57.41 81.62,57.41 81.41,57.61 81.41,58.02 81.62,58.22 83.38,58.22 83.58,58.42 83.58,58.83 83.38,59.03 82.71,59.03 82.5,59.25 82.5,59.79 85.7,63 85.7,63.77 87.53,65.6 87.53,66.15 88.12,66.73 88.6,66.73 89.58,67.72 96.22,67.72 96.82,68.32
  BOTTOM w0.102: UC4.F44 v3(100.33,68.56)
  BOTTOM w0.165: JDIMM1.74 91.43,39.19 v3(90.66,39.96)
DDR_A_CLK0: length 60.1
  IN2 w0.102: 99.96,61.47 99.96,61.5 99.94,61.51 99.94,62.04 101.28,63.37 101.28,63.99 101.53,64.24 102.04,64.24 102.29,64.5 102.29,66.67 102.39,66.77 102.66,66.77 v3(102.8,66.63)
  IN2 w0.127: v3(99.71,43.97) 100.13,44.4 100.13,45.52 99.96,45.7 99.96,58.92 99.62,59.25 99.11,59.25 98.66,58.8 98.66,52.06 98.44,51.83 98.12,51.83 97.9,52.06 97.9,58.17 97.52,58.55 96.98,58.55 96.6,58.17 96.6,53.39 96.46,53.24 96.06,53.24 95.84,53.47 95.84,58.43 98.3,60.88 99.64,60.88 99.96,61.2 99.96,61.47
  BOTTOM w0.102: UC4.M50 v3(102.8,66.63) ; JDIMM1.101 99.53,45.53 99.47,45.47 99.08,45.47 98.79,45.18 98.79,44.46 99.09,44.16 99.52,44.16 99.71,43.97 v3(99.71,43.97)
DDR_A_CLK0#: length 60.1
  IN2 w0.102: v3(102.81,67.25) 102.81,67.08 102.75,67.01 102.29,67.01 102.05,66.77 102.05,64.6 101.94,64.48 101.43,64.48 101.03,64.09 101.03,63.47 99.7,62.14 99.7,61.5 99.69,61.49 99.69,61.47
  IN2 w0.127: 99.69,61.47 99.69,61.31 99.53,61.15 98.19,61.15 95.57,58.54 95.57,53.36 95.95,52.98 96.57,52.98 96.87,53.28 96.87,58.06 97.09,58.28 97.41,58.28 97.63,58.06 97.63,51.95 98.01,51.57 98.55,51.57 98.93,51.95 98.93,58.69 99.22,58.99 99.51,58.99 99.69,58.8 99.69,45.59 99.87,45.41 99.87,44.8 99.71,44.65 v3(99.71,44.65)
  BOTTOM w0.102: v3(102.81,67.25) 102.99,67.42 103.14,67.42 103.32,67.24 UC4.M48 ; v3(99.71,44.65) 99.7,44.64 99.7,44.44 99.64,44.37 99.18,44.37 99,44.55 99,45.09 99.17,45.25 99.56,45.25 99.75,45.44 99.75,45.62 100.13,46 JDIMM1.103
DDR_A_CLK2: length 59.2
  IN2 w0.102: v3(103.78,66.01) 103.63,66.01 103.13,65.51 103.13,64.08 100.97,61.92 100.97,61.51 100.98,61.5 100.98,61.47
  IN2 w0.127: 100.98,61.47 100.98,49.59 101.16,49.41 101.16,43.51 99.3,41.65 99.3,39.07 98.71,38.49 98.71,36.58 99.1,36.2 104.18,36.2 104.44,36.46 107.91,36.46 108.14,36.69 108.14,37 107.91,37.23 100.38,37.23 100.07,37.53 100.07,40.88 v3(100.86,41.67)
  BOTTOM w0.102: JDIMM1.102 99.83,39.63 99.91,39.7 100.13,39.7 100.22,39.79 100.22,41.03 v3(100.86,41.67) ; UC4.P50 104.32,66.15 104.04,65.87 103.93,65.87 v3(103.78,66.01)
DDR_A_CLK2#: length 59.1
  IN2 w0.102: 100.72,61.47 100.72,61.5 100.73,61.51 100.73,62.02 102.89,64.18 102.89,65.61 103.33,66.06 103.33,66.06 103.81,66.68 v3(103.81,66.68)
  IN2 w0.127: v3(100.88,41.09) 100.65,41.09 100.34,40.77 100.34,37.64 100.49,37.49 108.02,37.49 108.4,37.11 108.4,36.58 108.02,36.2 104.55,36.2 104.29,35.93 98.98,35.93 98.44,36.47 98.44,38.6 99.03,39.18 99.03,41.76 100.89,43.62 100.89,49.3 100.72,49.48 100.72,61.47
  BOTTOM w0.102: v3(100.88,41.09) 100.58,41.09 100.43,40.94 JDIMM1.104 ; v3(103.81,66.68) UC4.P48
DDR_A_CS0#: length 60.1
  IN2 w0.102: v3(103.83,69.66) 104.39,70.23 104.39,70.4 104.65,70.65 104.97,70.65 106.07,69.55 106.07,64.46 107.6,62.93 107.6,62.11
  IN2 w0.203: v3(103.43,39.98) 103.98,40.53 105.33,40.53 105.98,41.18 106.67,41.18 107.53,42.04 108.96,42.04 109.65,42.73 109.65,43.39 109.84,43.59 110.95,43.59 111.24,43.88 111.24,44.16 110.6,44.8 110.6,45.15 111.22,45.76 112.26,45.76 112.52,45.5 112.52,42.68 112.72,42.47 113.64,42.47 113.89,42.72 113.89,45.56 114.09,45.76 114.29,45.76 114.49,45.96 114.49,46.37 114.29,46.57 112.54,46.57 112.3,46.81 112.3,47.15 112.54,47.38 114.96,47.38 115.64,48.07 115.64,52.56 114.59,53.6 113.11,53.6 107.6,59.11 107.6,62.11
  BOTTOM w0.102: UC4.P44 v3(103.83,69.66)
  BOTTOM w0.165: v3(103.43,39.98) JDIMM1.114
DDR_A_CS2#: length 60.1
  IN2 w0.102: 106.27,62.42 106.27,62.84 105.67,63.44 105.67,69.1 104.91,69.86 104.6,69.86 104.21,69.48 104.21,69.35 v3(103.83,68.97)
  IN2 w0.203: 106.27,62.42 106.27,58.72 109.46,55.53 109.46,51.66 109.02,51.22 108.36,51.22 107.83,50.69 107.83,49.42 108.07,49.19 108.41,49.19 108.64,49.42 108.64,50.1 108.9,50.35 109.24,50.35 109.46,50.13 109.46,48.11 109.69,47.87 110.03,47.87 110.27,48.11 110.27,53.91 110.51,54.15 110.84,54.15 111.76,53.23 111.76,52.84 111.08,52.17 111.08,47.35 110.33,46.59 110.04,46.59 109.61,47.02 109.01,47.02 108.8,47.23 108.8,47.55 108.6,47.75 108.19,47.75 107.99,47.55 107.99,47.23 107.79,47.02 107.32,47.02 107.04,46.74 107.04,46.41 107.25,46.21 108.98,46.21 109.22,45.96 109.22,45.62 109,45.4 107.46,45.4 107.26,45.19 107.26,44.93 106.79,44.46 v3(106.56,44.46)
  BOTTOM w0.102: UC4.P45 v3(103.83,68.97)
  BOTTOM w0.165: JDIMM1.121 105.53,45.22 106.29,44.46 v3(106.56,44.46)
DDR_A_D0: length 73.4
  IN1 w0.102: 100.44,73.96 102.02,73.96 103.13,72.85 v3(103.13,72.6)
  IN1 w0.127: v3(67.44,44.56) 67.24,44.76 67.24,46.74 66.86,47.12 66.86,65.16 67.03,65.33 67.27,65.33 67.44,65.16 67.44,62.88 67.61,62.71 67.86,62.71 68.03,62.88 68.03,66.38 78.15,76.51 92.54,76.51 93.43,75.62 93.65,75.62 93.81,75.77 93.81,75.98 93.97,76.14 94.29,76.14 94.69,75.75 94.69,75.39 94.92,75.15 98.4,75.15 99.04,74.5 99.6,74.5 100.14,73.96 100.44,73.96
  BOTTOM w0.102: UC4.M36 v3(103.13,72.6) ; v3(67.44,44.56) 68.1,44.56 68.33,44.78 JDIMM1.5
DDR_A_D1: length 73.4
  IN1 w0.102: v3(101.13,72.6) 101.13,72.69 100.75,73.07 98.97,73.07 98.67,72.77 98.36,72.77
  IN1 w0.127: 98.36,72.77 96.87,72.77 96.62,73.01 93.46,73.01 91.79,74.68 78.9,74.68 69.83,65.62 69.83,59.43 69.66,59.26 69.42,59.26 69.25,59.43 69.25,60.98 69.08,61.15 68.83,61.15 68.66,60.98 68.66,48.1 69.04,47.72 69.04,45.95 69.24,45.76 69.24,45.34 69.5,45.07 69.5,44.59 69.23,44.31 69.23,44 69.5,43.73 69.5,43.34 69.23,43.07 69.23,42.11 69.48,41.86 69.97,41.86 70.13,42.03 v3(70.13,43.84)
  BOTTOM w0.102: JDIMM1.7 68.93,43.65 69.35,43.24 69.86,43.24 70.13,43.51 v3(70.13,43.84) ; UC4.J36 v3(101.13,72.6)
DDR_A_D2: length 73.4
  IN1 w0.127: v3(71.41,43.85) 71.41,42.41 71.61,42.21 72.06,42.21 72.31,42.46 72.31,42.91 72.09,43.13 72.09,43.6 72.31,43.82 72.31,44.22 72.17,44.37 72.17,58.99 72.34,59.16 72.58,59.16 72.75,58.99 72.75,56.15 72.92,55.98 73.16,55.98 73.34,56.15 73.34,65.82 79.86,72.34 90.82,72.34 92.52,70.65 94.7,70.65 96.18,69.17 98.25,69.17 98.43,69.35 98.43,69.53 98.24,69.72 98.24,69.9 98.47,70.14 98.65,70.14 98.85,69.94 99.03,69.94 99.24,70.15 102.17,70.15 v3(103.57,71.55)
  BOTTOM w0.102: v3(71.41,43.85) 70.9,44.36 70.9,45.45 71.33,45.88 JDIMM1.15 ; UC4.P40 v3(103.57,71.55)
DDR_A_D3: length 73.3
  IN1 w0.102: v3(102.74,71.58) 102.29,71.13 101.92,71.13 101.82,71.02 98.5,71.02 98,70.52 97.79,70.52
  IN1 w0.127: v3(71.46,45.16) 71.46,45.16 71.54,45.24 71.54,46.83 71.41,46.97 70.97,46.97 70.8,47.14 70.8,47.38 70.97,47.55 71.41,47.55 71.53,47.68 71.53,48.01 71.41,48.13 70.98,48.13 70.85,48.26 70.85,48.59 70.98,48.72 71.41,48.72 71.53,48.85 71.53,49.18 71.41,49.3 70.71,49.3 70.54,49.47 70.54,49.72 70.71,49.89 71.41,49.89 71.58,50.06 71.58,64.88 71.75,65.05 72,65.05 72.17,64.88 72.17,59.92 72.34,59.75 72.58,59.75 72.75,59.92 72.75,66.06 79.62,72.93 91.07,72.93 92.74,71.26 94.96,71.26 96.23,69.99 96.56,69.99 96.92,70.34 97.25,70.34 97.43,70.52 97.79,70.52
  BOTTOM w0.102: UC4.M40 v3(102.74,71.58) ; v3(71.46,45.16) 71.93,45.63 JDIMM1.17
DDR_A_D4: length 73.6
  IN1 w0.102: 97.06,76.79 98.29,76.52 102.06,74.83 v3(104.32,72.58)
  IN1 w0.127: 97.06,76.79 96.99,76.81 96.17,76.89 93.27,77.68 77.67,77.68 65.69,65.7 65.69,46.49 66.07,46.11 66.07,43.57 66.53,43.11 66.53,42.02 v3(66.76,41)
  BOTTOM w0.102: JDIMM1.4 68.03,39.58 67.98,39.65 67.02,40.75 v3(66.76,41) ; UC4.P36 v3(104.32,72.58)
DDR_A_D5: length 73.1
  IN1 w0.102: 98.34,75.79 98.72,75.79 99.33,75.18 99.96,75.18 100.25,74.88 100.67,74.88 101.05,74.5 101.81,74.5 v3(103.72,72.6)
  IN1 w0.127: v3(67.44,43.15) 67.32,43.15 66.66,43.81 66.66,46.36 66.27,46.74 66.27,65.46 77.91,77.09 92.78,77.09 93.15,76.73 94.53,76.73 95.27,75.99 97.37,75.99 97.57,75.79 98.34,75.79
  BOTTOM w0.102: UC4.N36 103.74,72.62 v3(103.72,72.6) ; JDIMM1.6 68.63,39.88 67.77,40.74 67.77,41.48 66.96,42.29 66.96,42.93 67.17,43.15 v3(67.44,43.15)
DDR_A_D6: length 73.4
  IN1 w0.102: v3(102.06,71.61) 101.68,71.22 97.65,71.22
  IN1 w0.127: v3(72.29,41.67) 71.81,41.19 71.81,39.12 71.46,38.77 69.89,38.77 69.71,38.95 69.71,39.21 69.89,39.4 70.95,39.4 71.2,39.65 71.2,41.05 70.77,41.48 70.77,45.98 70.21,46.54 70.21,48.21 69.83,48.59 69.83,49.84 71,51 71,65.13 79.38,73.51 91.31,73.51 92.98,71.84 95.46,71.84 96.35,70.94 97.03,70.94 97.31,71.22 97.65,71.22
  BOTTOM w0.102: UC4.K40 v3(102.06,71.61) ; JDIMM1.16 71.63,41.01 v3(72.29,41.67)
DDR_A_D7: length 73.3
  IN1 w0.127: v3(101.95,69.56) 101.55,69.16 99.07,69.16 98.84,68.92 98.5,68.58 96.8,68.58 96.63,68.41 96.63,66.82 96.44,66.63 96.18,66.63 95.99,66.82 95.99,68.53 94.47,70.05 92.29,70.05 90.58,71.76 80.3,71.76 73.92,65.38 73.92,55.91 72.75,54.74 72.75,44.61 72.9,44.46 72.9,40.83 73.09,40.64 73.09,38.57 72.07,37.55 70.33,37.55 70.14,37.73 70.14,38 70.33,38.18 71.71,38.18 72.45,38.92 v3(72.45,40.14)
  BOTTOM w0.102: UC4.K42 v3(101.95,69.56) ; JDIMM1.18 72.23,39.92 v3(72.45,40.14)
DDR_A_D8: length 57.2
  IN1 w0.127: v3(84.8,71.03) 84.8,70.85 83.86,69.91 81.13,69.91 80.75,70.29 80.48,70.29 76.26,66.06 76.26,64.26 76.09,64.09 75.84,64.09 75.67,64.26 75.67,64.83 75.5,65 75.26,65 75.09,64.83 75.09,50.85 74.92,50.68 74.68,50.68 74.5,50.85 74.5,51.26 74.33,51.43 74.09,51.43 73.92,51.26 73.92,44.76 73.64,44.48 v3(73.64,43.59)
  BOTTOM w0.102: v3(73.64,43.59) 72.75,44.48 72.75,45.6 73.13,45.98 JDIMM1.21 ; UC4.B32 97.57,75.02 97.35,74.8 95.07,74.8 93.68,73.41 87.18,73.41 v3(84.8,71.03)
DDR_A_D9: length 57.1
  IN1 w0.127: v3(73.34,45.33) 73.34,54.5 73.51,54.67 73.75,54.67 73.92,54.5 73.92,52.19 74.09,52.01 74.33,52.01 74.5,52.19 74.5,65.13 80.24,70.87 81.43,70.87 81.8,70.5 82.24,70.5 82.35,70.62 82.35,70.85 82.48,70.98 82.94,70.98 83.22,70.69 83.45,70.69 83.6,70.85 v3(83.6,71.09)
  BOTTOM w0.102: v3(73.34,45.33) 73.31,45.33 73.73,45.75 JDIMM1.23 ; v3(83.6,71.09) 84.06,71.56 84.42,71.56 86.83,73.97 93.86,73.97 94.96,75.07 97.27,75.07 97.42,75.22 98,75.22 98.1,75.32 98.34,75.32 98.64,75.02 UC4.C32
DDR_A_D10: length 57.2
  IN1 w0.127: v3(92.78,69.43) 92.78,68.82 91.99,68.03 87.93,68.03 86.65,66.74 86.65,62.47 83.71,59.53 81.87,59.53 81.59,59.25 81.59,54.86 81.42,54.69 81.18,54.69 81.01,54.86 81.01,57.26 80.84,57.43 80.59,57.43 80.42,57.26 80.42,50.26 80.25,50.09 80.01,50.09 79.84,50.26 79.84,50.51 79.67,50.68 79.43,50.68 79.25,50.51 79.25,49.08 78.21,48.04 78.21,46.82 78.38,46.64 78.63,46.64 78.8,46.82 78.8,47.51 78.97,47.68 79.21,47.68 79.38,47.51 79.38,46.11 78.82,45.55 78.82,44.4 v3(78.16,43.74)
  BOTTOM w0.102: UC4.C36 98.65,73.08 98.35,72.77 98.1,72.77 98,72.87 96.05,72.87 92.78,69.61 v3(92.78,69.43) ; JDIMM1.33 76.73,45.54 77.46,44.82 77.46,44.45 v3(78.16,43.74)
DDR_A_D11: length 56.9
  IN1 w0.127: v3(78.03,45.03) 78.03,46.17 77.46,46.74 77.46,48.12 78.67,49.32 78.67,57.42 78.84,57.59 79.08,57.59 79.25,57.42 79.25,51.52 79.43,51.35 79.67,51.35 79.84,51.52 79.84,57.54 81.01,58.7 81.01,59.75 81.37,60.11 83.46,60.11 86.06,62.71 86.06,66.99 87.69,68.62 91.72,68.62 92.11,69.01 v3(92.11,69.42)
  BOTTOM w0.102: UC4.A37 97.83,72.59 96.13,72.59 93.21,69.67 93.21,69.31 92.78,68.89 92.34,68.89 92.11,69.12 v3(92.11,69.42) ; JDIMM1.35 77.33,45.73 v3(78.03,45.03)
DDR_A_D12: length 57.8
  IN1 w0.127: v3(74.03,41.46) 74.03,41.26 73.9,41.12 73.85,41.07 73.62,41.07 73.48,41.2 73.48,42.56 73.74,42.81 74.28,42.81 74.5,43.04 74.5,43.4 74.25,43.66 74.25,44.27 74.5,44.52 74.5,49.37 75.7,50.57 75.7,63.34 75.87,63.51 76.14,63.51 76.33,63.31 76.33,63.09 76.51,62.91 76.76,62.91 76.94,63.09 76.94,65.92 80.22,69.19 83.97,69.19 85.73,70.95 v3(85.73,71.16)
  BOTTOM w0.102: JDIMM1.22 73.43,40.86 v3(74.03,41.46) ; v3(85.73,71.16) 87.41,72.84 93.49,72.84 95.2,74.55 97.39,74.55 97.65,74.82 97.99,74.82 98.28,74.53 UC4.C33
DDR_A_D13: length 57.2
  IN1 w0.127: v3(74.03,39.94) 73.74,39.65 73.74,38.09 74,37.84 74.38,37.84 74.63,38.09 74.63,42.34 75.09,42.79 75.09,49.13 76.29,50.33 76.29,61.61 77.65,62.97 77.65,65.8 80.46,68.61 84.25,68.61 v3(86.54,70.91)
  BOTTOM w0.102: JDIMM1.24 74.03,39.94 v3(74.03,39.94) ; UC4.A33 97.62,74.32 95.41,74.32 93.34,72.24 87.88,72.24 v3(86.54,70.91)
DDR_A_D14: length 56.9
  IN1 w0.127: v3(77.48,41.23) 77.04,40.8 77.04,38.63 76.87,38.46 76.63,38.46 76.46,38.63 76.46,42.64 76.95,43.14 77.2,43.14 77.37,42.96 77.37,42.72 77.1,42.45 77.1,42.14 77.3,41.94 78.01,41.94 78.62,42.55 78.62,43.31 79.97,44.66 79.97,48.97 81.01,50.01 81.01,53.45 82.18,54.62 82.18,58.43 82.69,58.95 83.95,58.95 87.23,62.23 87.23,66.5 88.17,67.45 92.27,67.45 93.64,68.81 v3(93.64,69.45)
  BOTTOM w0.102: v3(77.48,41.23) 77.03,40.78 JDIMM1.34 ; v3(93.64,69.45) 96.49,72.31 98,72.31 98.11,72.41 98.4,72.41 UC4.C37
DDR_A_D15: length 55.6
  IN1 w0.127: v3(94.28,69.37) 94.28,68.63 92.51,66.86 89.95,66.86 88.52,66.86 87.81,66.16 87.81,61.98 84.19,58.36 83.23,58.36 82.76,57.9 82.76,54.38 81.59,53.21 81.59,49.77 80.55,48.73 80.55,44.42 80.02,43.88 80.02,43.4 79.89,43.27 79.5,43.27 79.33,43.1 79.33,42.86 79.5,42.69 79.89,42.69 80.02,42.56 80.02,39 79.83,38.82 79.6,38.82 79.43,38.98 79.43,41.64 79.18,41.9 78.83,41.9 78.31,41.37 78.31,39.04 78.11,38.85 77.83,38.85 77.63,39.06 v3(77.63,39.96)
  BOTTOM w0.102: JDIMM1.36 77.63,39.96 v3(77.63,39.96) ; UC4.B38 98.15,72.04 97,72.04 94.34,69.37 v3(94.28,69.37)
DDR_A_D16: length 72.2
  IN2 w0.102: v3(99.73,72.57) 99.7,72.57 97.87,74.4 95.64,74.4
  IN2 w0.127: 95.64,74.4 78.22,74.4 69.65,65.83 69.65,64.06 69.82,63.89 70.07,63.89 70.24,64.06 70.24,65.49 70.41,65.66 70.65,65.66 70.82,65.49 70.82,52.34 71.81,51.36 71.99,51.36 72.47,51.84 72.71,51.84 72.88,51.66 72.88,51.42 72.4,50.94 72.4,50.76 77.48,45.69 77.48,42.88 v3(77.86,42.5)
  BOTTOM w0.102: JDIMM1.39 78.53,45.72 78.87,45.38 78.87,43.29 78.09,42.5 v3(77.86,42.5) ; UC4.F36 v3(99.73,72.57)
DDR_A_D17: length 72.8
  IN2 w0.102: v3(100.49,71.63) 100.49,71.56 100.18,71.25 98.99,71.25 98.77,71.46 98.77,71.89 97.78,72.89 96.36,72.89 96.02,73.23 95.15,73.23
  IN2 w0.127: v3(79.43,45.29) 79.43,45.39 74.22,50.59 74.22,54.4 74.1,54.53 72.12,54.53 71.99,54.66 71.99,54.99 72.12,55.11 74.11,55.11 74.22,55.22 74.22,55.55 74.08,55.7 72.12,55.7 71.99,55.83 71.99,56.16 72.12,56.28 74.09,56.28 74.22,56.42 74.22,56.75 74.11,56.87 72.12,56.87 71.99,56.99 71.99,57.32 72.12,57.45 74.1,57.45 74.22,57.58 74.22,57.91 74.1,58.03 72.12,58.03 71.99,58.16 71.99,66.52 78.71,73.23 95.15,73.23
  BOTTOM w0.102: v3(79.43,45.29) 79.43,45.61 79.13,45.91 JDIMM1.41 ; UC4.G38 v3(100.49,71.63)
DDR_A_D18: length 73.3
  IN2 w0.102: 97.46,71.08 97.79,71.08 98.86,70.01 99.55,70.01 99.69,70.15 100.17,70.15 v3(100.61,70.59)
  IN2 w0.127: 97.46,71.08 96.2,71.08 95.6,70.48 88.28,70.48 87.25,69.46 79.22,69.46 76.6,66.84 76.6,51.95 77.7,50.85 77.88,50.85 78.09,51.06 78.09,51.29 77.18,52.19 77.18,60.61 77.31,60.74 77.64,60.74 77.77,60.61 77.77,52.43 78.98,51.22 78.98,49.57 82.49,46.06 v3(82.49,45.4)
  BOTTOM w0.102: UC4.F42 v3(100.61,70.59) ; JDIMM1.51 82.13,45.76 82.49,45.4 v3(82.49,45.4)
DDR_A_D19: length 73.8
  IN2 w0.102: v3(101.37,69.63) 101.37,69.63 100.78,69.04 98.22,69.04 97.88,69.38 97.75,69.38
  IN2 w0.127: v3(84,43.92) 84.21,43.92 84.74,43.39 84.74,38.93 84.92,38.75 85.18,38.75 85.36,38.93 85.36,45.84 80.79,50.41 80.79,61.24 80.62,61.41 80.38,61.41 80.21,61.24 80.21,57.38 80.04,57.21 79.79,57.21 79.62,57.38 79.62,62 78.51,63.11 78.51,66.27 79.93,67.69 88.64,67.69 89.31,68.36 95.98,68.36 97,69.38 97.75,69.38
  BOTTOM w0.102: v3(101.37,69.63) 101.37,69.63 101.61,69.86 UC4.J42 ; JDIMM1.53 82.73,45.95 83.17,45.52 83.17,44.33 83.57,43.92 v3(84,43.92)
DDR_A_D20: length 73.4
  IN2 w0.102: 95.15,74.99 95.85,74.99 96.23,74.6 97.95,74.6 99.36,73.2 99.71,73.2 100.14,72.78 100.14,72.36 100.28,72.22 100.77,72.22 v3(101.31,71.68)
  IN2 w0.127: 95.15,74.99 77.9,74.99 68.93,66.02 68.93,61.96 69.08,61.82 69.51,61.82 69.65,61.96 69.65,63.13 69.82,63.3 70.07,63.3 70.24,63.13 70.24,52.1 76.86,45.48 76.86,42.64 78.16,41.33 78.16,40.65 v3(78.9,39.91)
  BOTTOM w0.102: UC4.G40 v3(101.31,71.68) ; v3(78.9,39.91) 78.83,39.84 JDIMM1.40
DDR_A_D21: length 72.5
  IN2 w0.102: v3(99.21,71.68) 99.21,71.87 98.58,72.5 98.58,72.92 97.4,74.11 96.91,74.11 96.65,73.84 96.12,73.84 96.09,73.82
  IN2 w0.127: v3(78.84,41.2) 78.84,42.05 79.09,42.3 79.61,42.3 79.78,42.48 79.78,42.72 79.61,42.89 78.97,42.89 78.8,43.06 78.8,43.29 78.98,43.47 79.45,43.47 79.62,43.64 79.62,43.89 79.45,44.06 78.79,44.06 78.61,44.24 78.61,45.38 73.62,50.38 73.62,52.49 73.42,52.69 71.53,52.69 71.41,52.81 71.41,53.14 71.53,53.27 73.47,53.27 73.64,53.44 73.64,53.68 73.47,53.86 71.53,53.86 71.41,53.98 71.41,66.76 78.47,73.82 96.09,73.82
  BOTTOM w0.102: v3(78.84,41.2) 79.61,40.43 79.61,39.71 79.43,39.53 JDIMM1.42 ; UC4.C38 v3(99.21,71.68)
DDR_A_D22: length 73.4
  IN2 w0.102: 96.69,69.89 97.01,70.21 97.72,70.21 98.65,69.29 100.46,69.29 100.78,69.61 100.78,69.61 100.78,69.64 v3(100.78,69.64)
  IN2 w0.127: 96.69,69.89 95.74,68.94 88.93,68.94 88.28,68.29 79.7,68.29 77.93,66.52 77.93,62.87 79.04,61.76 79.04,52.82 79.21,52.65 79.45,52.65 79.62,52.82 79.62,56.45 79.77,56.6 80.06,56.6 80.21,56.45 80.21,50.17 84.09,46.28 84.09,45.4 83.58,44.89 83.58,44.32 83.42,44.16 83.42,41.81 83.76,41.47 83.76,37.88 83.61,37.73 83.26,37.73 83.11,37.88 83.11,40.95 v3(82.44,41.62)
  BOTTOM w0.102: UC4.G44 100.89,69.47 100.78,69.61 100.78,69.61 100.78,69.64 v3(100.78,69.64) ; JDIMM1.50 81.83,41.01 v3(82.44,41.62)
DDR_A_D23: length 73.4
  IN2 w0.102: 96.18,70.21 96.62,70.65 97.79,70.65 98.82,69.62 99.73,69.62 v3(99.81,69.7)
  IN2 w0.127: 96.18,70.21 95.87,69.9 88.52,69.9 87.49,68.87 79.46,68.87 77.34,66.76 77.34,62.62 78.45,61.51 78.45,52.57 79.62,51.41 79.62,49.93 83.07,46.48 83.07,45.18 82.98,45.08 82.98,44.65 82.84,44.51 82.84,43.13 81.43,41.73 81.43,39.18 81.26,39.01 75.01,39.01 74.84,38.84 74.84,38.6 75.01,38.43 82.12,38.43 82.43,38.74 v3(82.43,40.11)
  BOTTOM w0.102: JDIMM1.52 v3(82.43,40.11) ; UC4.D42 v3(99.81,69.7)
DDR_A_D24: length 48.4
  IN1 w0.127: v3(83.93,42.63) 84.33,42.23 84.33,41.93 84.2,41.8 83.88,41.8 82.7,42.98 82.7,43.22 82.82,43.34 83.42,43.34 83.58,43.51 83.58,43.74 83.42,43.9 83.12,43.9 83,44.03 83,44.42 83.34,44.77 83.34,46.26 83.22,46.39 82.47,46.39 82.34,46.51 82.34,46.84 82.47,46.97 83.22,46.97 83.34,47.1 83.34,47.43 83.22,47.55 82.47,47.55 82.34,47.68 82.34,48.01 82.47,48.14 83.22,48.14 83.34,48.27 83.34,52.48 84.51,53.65 84.51,56.2 89.57,61.26 89.57,64.66 89.92,65.02 v3(89.92,65.71)
  BOTTOM w0.102: UC4.A41 97.72,70.76 96.92,70.76 94.64,68.48 93.33,68.48 92.26,67.42 91.09,67.42 89.92,66.25 v3(89.92,65.71) ; JDIMM1.57 83.93,45.45 84.64,44.75 84.64,43.19 84.08,42.63 v3(83.93,42.63)
